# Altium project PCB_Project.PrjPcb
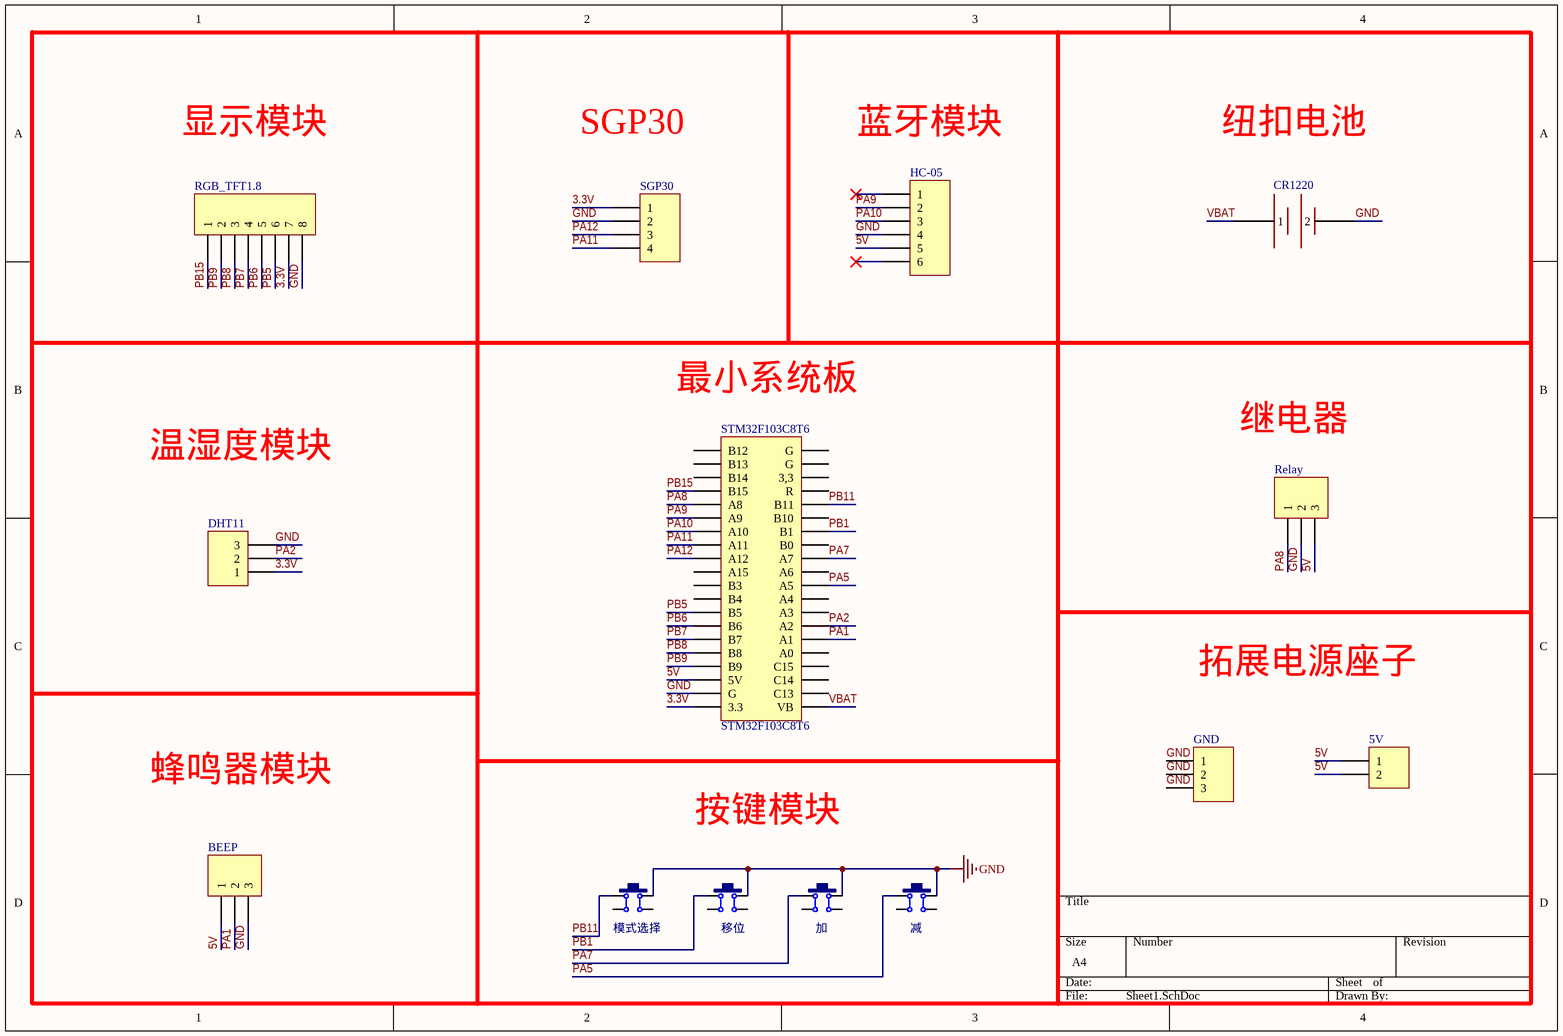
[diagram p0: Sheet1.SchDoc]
1 sheet, 14 parts. Net scope: global (net labels, ports and power ports of the same name join across sheets).
Board file: PCB1.PcbDoc

## Sheet Sheet1.SchDoc
size A4

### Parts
5V  5V座子  [HDR1X2]  (value not drawn)
BEEP  BEEP  [HDR1X3]  (value not drawn)
CR1220  CR1220  [CR1220]  (value not drawn)
DHT11  DHT11  [HDR1X3]  (value not drawn)
GND  GND座子  [HDR1X3]  (value not drawn)
HC-05  HC-05  [HDR1X6]  (value not drawn)
Relay  (no value)  [HDR1X3]
RGB_TFT1.8  RGB_TFT1.8  [HDR1X8]  (value not drawn)
SGP30  SGP30  [HDR1X4]  (value not drawn)
STM32F103C8T6  STM32F103C8T6  [DIP40-600_MH]
减  12x12x5  [TSW DIP-6*6*6]  (value not drawn)
加  12x12x5  [TSW DIP-6*6*6]  (value not drawn)
模式选择  12x12x5  [TSW DIP-6*6*6]  (value not drawn)
移位  12x12x5  [TSW DIP-6*6*6]  (value not drawn)

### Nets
GND: BEEP.3 CR1220.2 DHT11.3 GND.1 GND.2 GND.3 HC-05.4 Relay.2 RGB_TFT1.8.8 SGP30.2 STM32F103C8T6.19(G) 减.2 加.2 模式选择.2 移位.2
3.3V: DHT11.1 RGB_TFT1.8.7 SGP30.1 STM32F103C8T6.20(3.3)
5V: 5V.1 5V.2 BEEP.1 HC-05.5 Relay.3 STM32F103C8T6.18(5V)
PA1: BEEP.2 STM32F103C8T6.26(A1)
PA2: DHT11.2 STM32F103C8T6.27(A2)
PA5: STM32F103C8T6.30(A5) 减.1
PA7: STM32F103C8T6.32(A7) 加.1
PA8: Relay.1 STM32F103C8T6.5(A8)
PA9: HC-05.2 STM32F103C8T6.6(A9)
PA10: HC-05.3 STM32F103C8T6.7(A10)
PA11: SGP30.4 STM32F103C8T6.8(A11)
PA12: SGP30.3 STM32F103C8T6.9(A12)
PB1: STM32F103C8T6.34(B1) 移位.1
PB5: RGB_TFT1.8.6 STM32F103C8T6.13(B5)
PB6: RGB_TFT1.8.5 STM32F103C8T6.14(B6)
PB7: RGB_TFT1.8.4 STM32F103C8T6.15(B7)
PB8: RGB_TFT1.8.3 STM32F103C8T6.16(B8)
PB9: RGB_TFT1.8.2 STM32F103C8T6.17(B9)
PB11: STM32F103C8T6.36(B11) 模式选择.1
PB15: RGB_TFT1.8.1 STM32F103C8T6.4(B15)
VBAT: CR1220.1 STM32F103C8T6.21(VB)

Not connected (* = marked no-connect by the designer): HC-05 1* 6*; STM32F103C8T6 1(B12) 2(B13) 3(B14) 10(A15) 11(B3) 12(B4) 22(C13) 23(C14) 24(C15) 25(A0) 28(A3) 29(A4) 31(A6) 33(B0) 35(B10) 37(R) 38(3,3) 39(G) 40(G); 减 3 4; 加 3 4; 模式选择 3 4; 移位 3 4

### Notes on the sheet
- 显示模块
- SGP30
- 蓝牙模块
- 纽扣电池
- 最小系统板
- 继电器
- 温湿度模块
- 拓展电源座子
- 蜂鸣器模块
- 按键模块

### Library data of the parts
5V = Header 2: Header, 2-Pin
BEEP DHT11 GND Relay = Header 3: Header, 3-Pin
CR1220 = CR1220: 纽扣电池
HC-05 = Header 6: Header, 6-Pin
RGB_TFT1.8 = Header 8: Header, 8-Pin
SGP30 = Header 4: Header, 4-Pin
STM32F103C8T6 = STM32F103C8T6: 最小系统板
减 加 模式选择 移位 = TSW DIP-12x12: 直插12x12轻触开关; 版权归属: 封装库来自淘宝 ID：黄晶宝石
